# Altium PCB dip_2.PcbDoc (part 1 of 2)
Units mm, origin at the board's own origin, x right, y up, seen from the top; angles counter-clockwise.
Board outline 62.5 x 72.5 mm, 2 copper layers (Top Layer, Bottom Layer); 36 components, 64 nets, 215 pads, 49 vias.
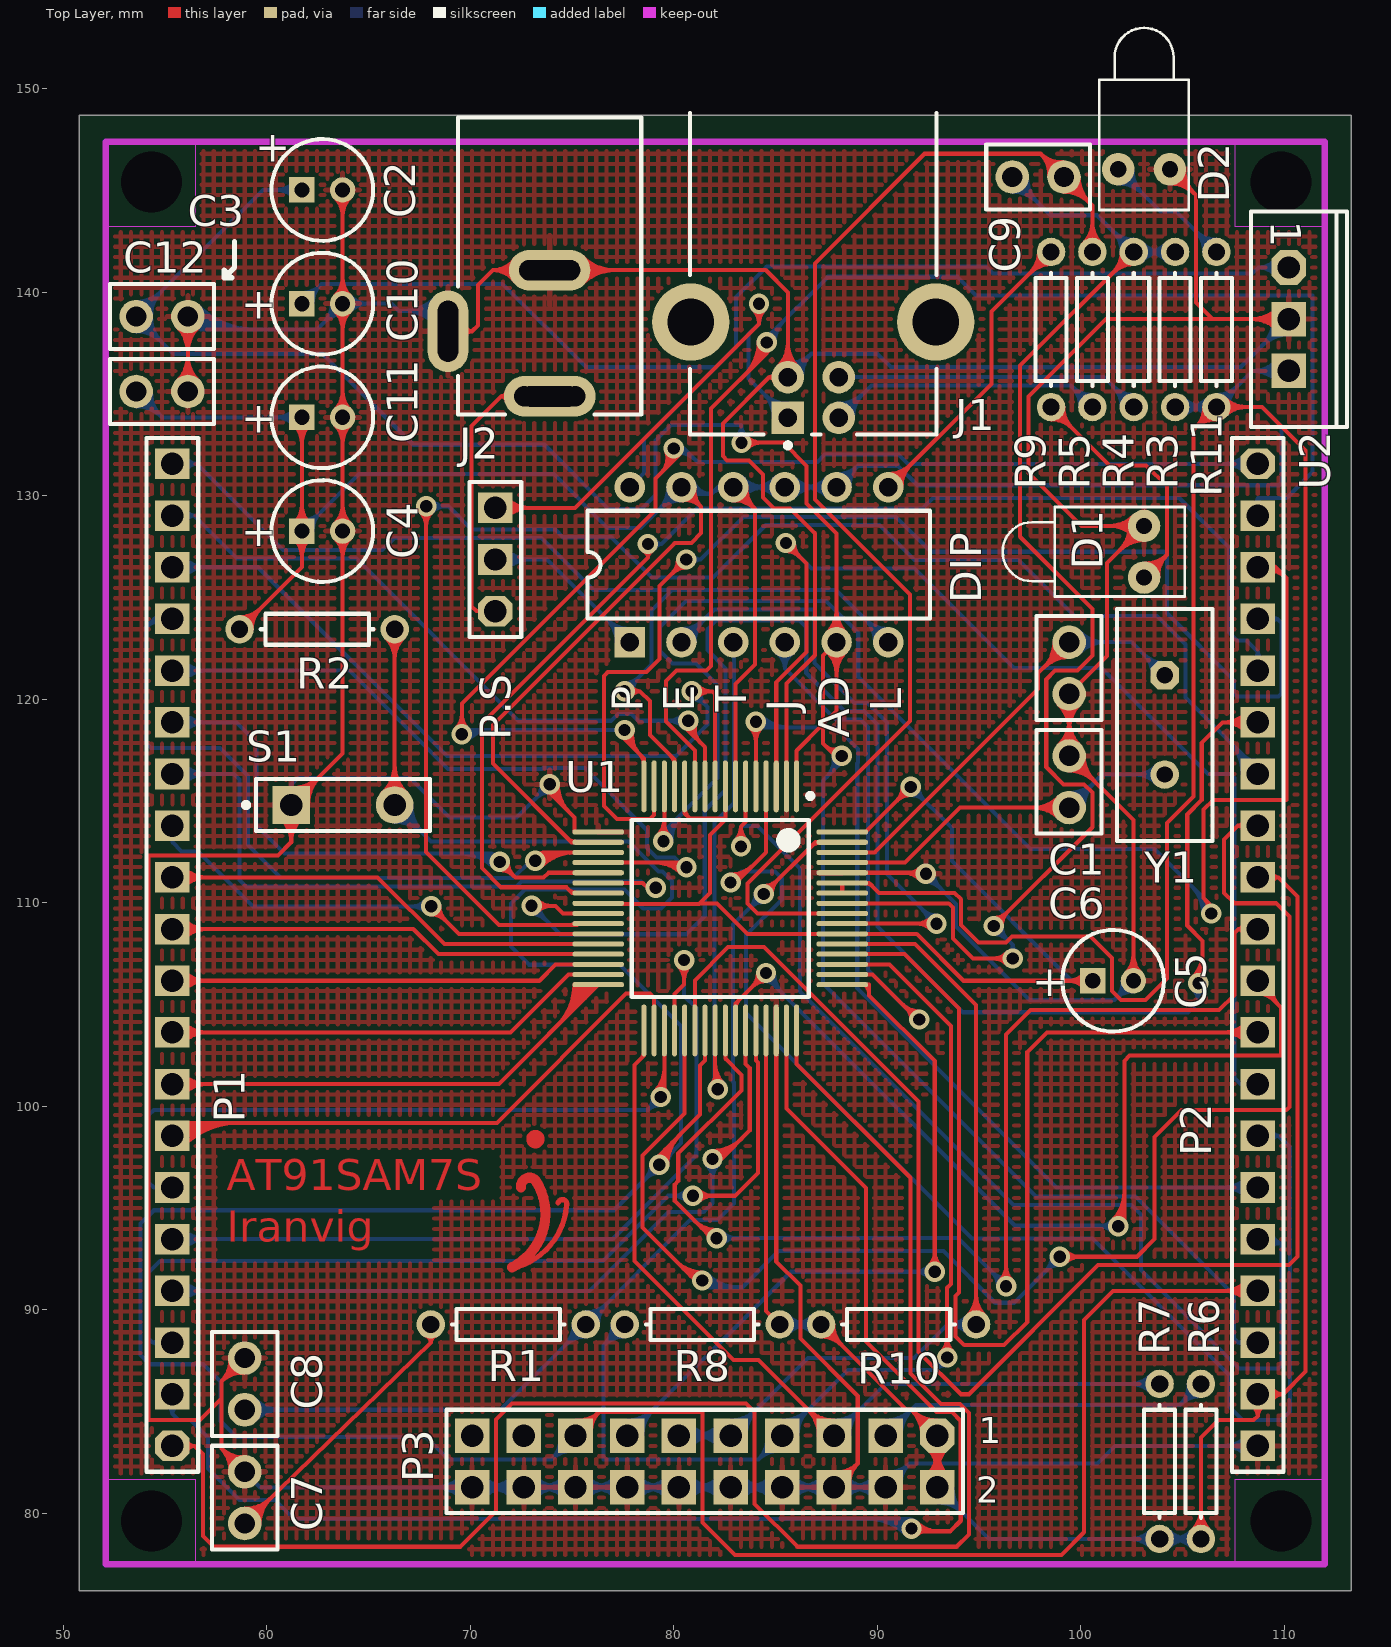
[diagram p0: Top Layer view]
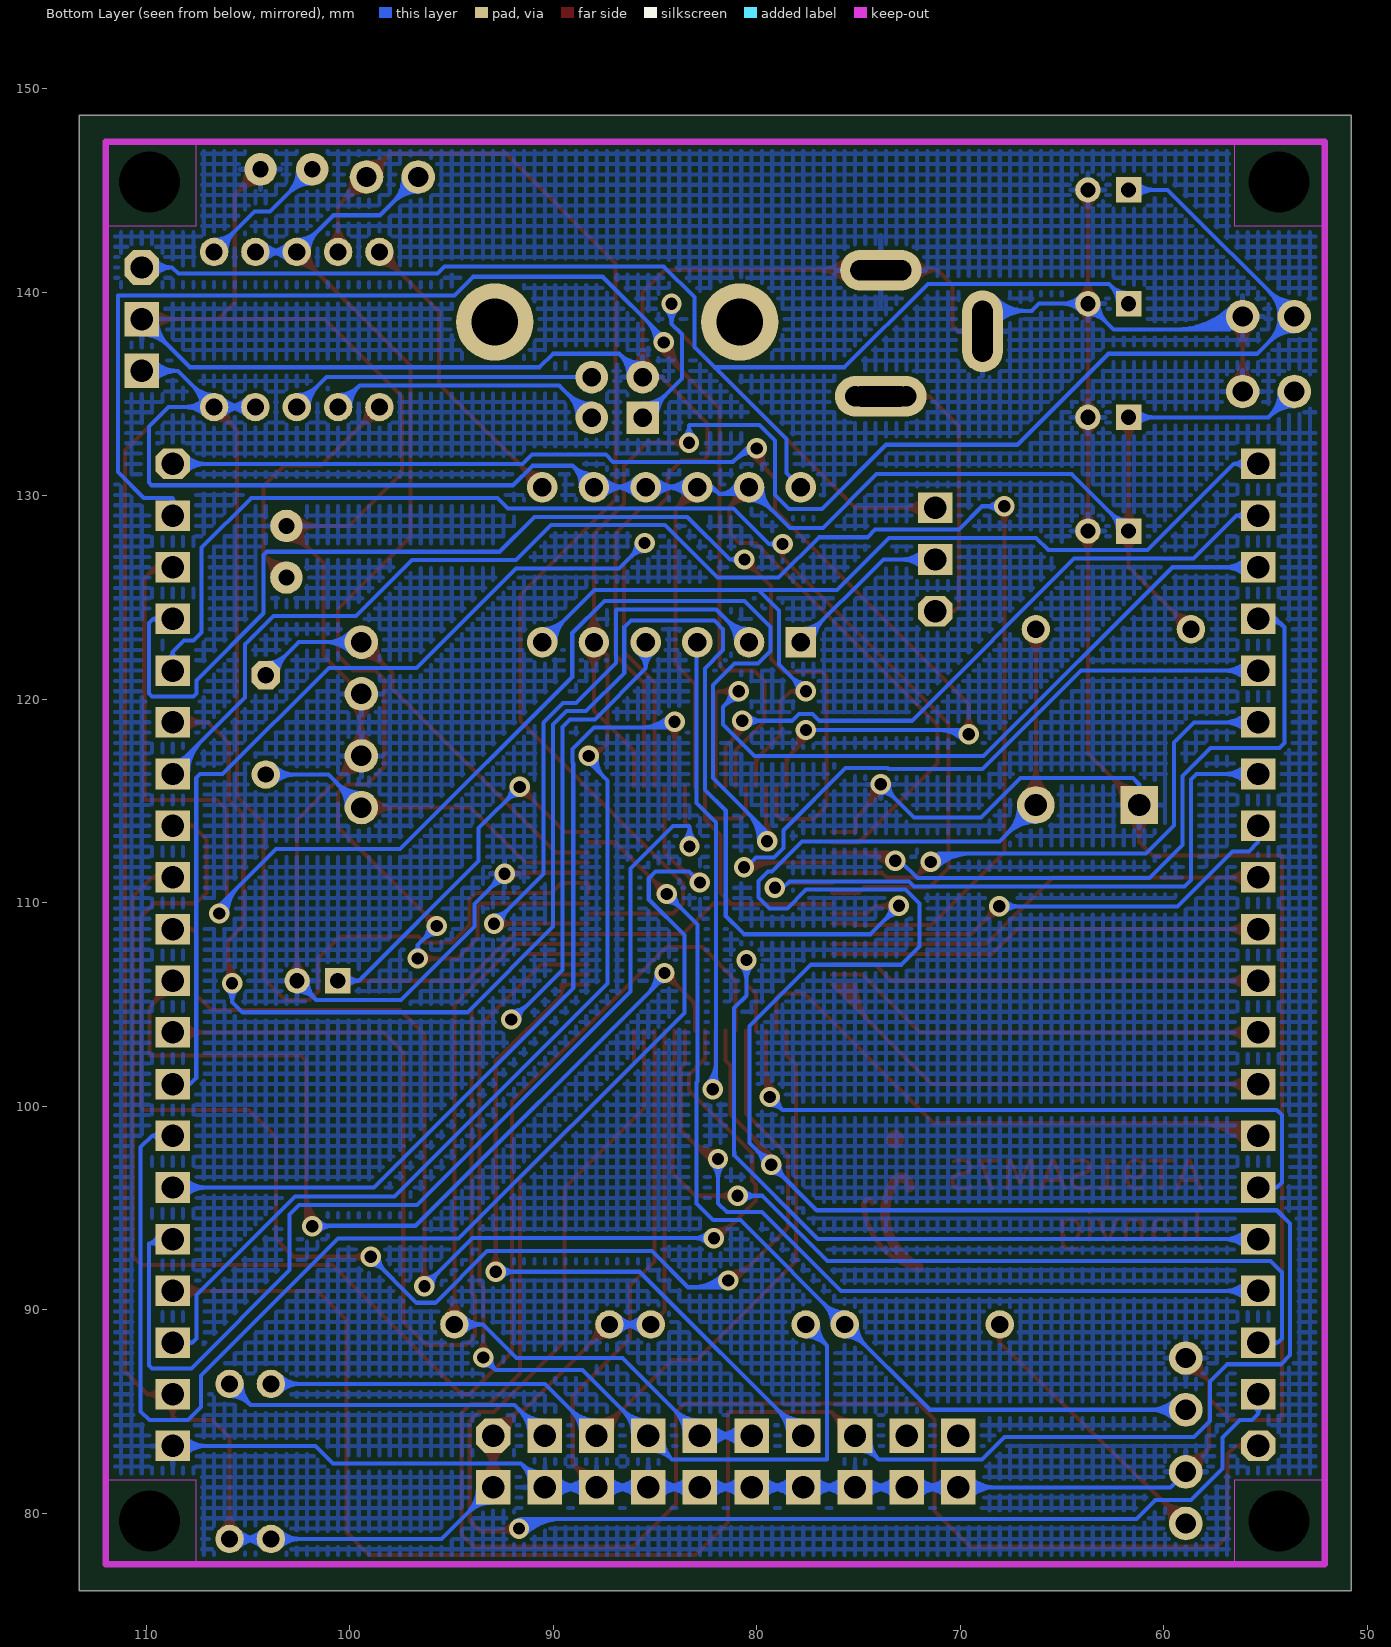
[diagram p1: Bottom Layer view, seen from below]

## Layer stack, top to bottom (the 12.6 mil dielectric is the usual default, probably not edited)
Top Layer: signal copper 0.0356
Dielectric: dielectric 0.32, FR-4, Dk 4.8
Bottom Layer: signal copper 0.0356

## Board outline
50.8,76.2 113.3,76.2 113.3,148.7 50.8,148.7

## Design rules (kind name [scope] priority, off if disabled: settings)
Clearance [All] p1: gap=0.2
PolygonConnect [All] p1: connectstyle=Relief reliefconductorwidth=0.254 reliefentries=4 polygonreliefangle="90 Angle"
RoutingVias [All] p1: holewidth=0.6 width=1 viastyle="Through Hole" minholewidth=0.711 minwidth=1.27 maxholewidth=0.711 maxwidth=1.27
SMDNeckDown [All] p1: percent=100.000
SMDToCorner [All] p1: distance=1181102
SilkscreenOverComponentPads [All] p1: minsilkscreentomaskgap=0.254
SolderMaskExpansion [All] p1: expansion=0.102
TestPointUsage [All] p1: valid=0 allowmultiple=FALSE
Testpoint [All] p1: side=15 testpointundercomponent=TRUE minsize=1.016 maxsize=2.54 preferedsize=1.524 minholesize=0 maxholesize=1.016 preferedholesize=0.813 testpointgrid=0.025 style=1023 order=0123456789
Width [All] p1: maxlimit=0.2 minlimit=0.2 preferedwidth=0.2
23 further rules are at their usual default settings.

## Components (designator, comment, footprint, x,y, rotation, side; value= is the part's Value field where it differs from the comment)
C1 "Cap" VP32-3.2 99.441,121.539 r270 top
C2 "Cap Pol1" B 62.738,145.034 r0 top
C3 "Cap" VP32-3.2 54.864,138.811 r180 top
C4 "Cap Pol1" B 62.738,128.27 r0 top
C5 "Cap Pol1" B 101.6,106.172 r0 top
C6 "Cap" VP32-3.2 99.441,115.951 r90 top
C7 "Cap" VP32-3.2 58.928,80.772 r90 top
C8 "Cap" VP32-3.2 58.928,86.36 r90 top
C9 "Cap" VP32-3.2 97.917,145.669 r180 top
C10 "Cap Pol1" B 62.738,139.446 r0 top
C11 "Cap Pol1" B 62.738,133.858 r0 top
C12 "Cap" VP32-3.2 54.864,135.128 r180 top
D1 "LED1" LED-1 103.124,127.254 r180 top
D2 "LED1" LED-1 103.124,146.05 r90 top
DIP "SW DIP-6" DIP-12/SW 84.201,126.619 r0 top (schematic designator DIPs)
J1 "1470156-1" 1470156 86.868,148.844 r90 top
J2 "PWR2.5" KLD-0202 73.914,148.59 r270 top
P1 "Header 20" HDR1X20 55.372,83.312 r90 top
P2 "Header 20" HDR1X20 108.712,131.572 r270 top
P3 "Header 10X2" HDR2X10 92.964,83.82 r180 top
P.S "Header 3" HDR1X3 71.247,124.333 r90 top (schematic designator PWR.S)
R1 "Res1" AXIAL-0.3 71.882,89.281 r180 top
R2 "Res1" AXIAL-0.3 62.484,123.444 r180 top
R3 "Res1" AXIAL-0.3 104.648,138.176 r90 top
R4 "Res1" AXIAL-0.3 102.616,138.176 r90 top
R5 "Res1" AXIAL-0.3 100.584,138.176 r90 top
R6 "Res1" AXIAL-0.3 105.918,82.55 r90 top
R7 "Res1" AXIAL-0.3 103.886,82.55 r90 top
R8 "Res1" AXIAL-0.3 81.407,89.281 r180 top
R9 "Res1" AXIAL-0.3 98.552,138.176 r90 top
R10 "Res1" AXIAL-0.3 91.059,89.281 r0 top
R11 "Res1" AXIAL-0.3 106.68,138.176 r90 top (schematic designator R13)
S1 "SW-PB" SPST-2 63.754,114.808 r0 top
U1 "AT91SAM7S256-AU-001" LQFP64_L 82.296,109.728 r270 top
U2 "LF33ACV" TO-220A 110.236,138.684 r270 top
Y1 "18.432 MHz" HC-49U 104.14,118.745 r270 top

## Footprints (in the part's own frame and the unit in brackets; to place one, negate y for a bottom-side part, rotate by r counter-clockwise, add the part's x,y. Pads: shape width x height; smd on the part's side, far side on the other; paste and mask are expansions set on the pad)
1470156 [mm] "Connector; USB1.1, Type B, Thru-Hole; 4 Position; Right Angle"
  rect 1.6x1.6 hole 0.92: 1(-15.01,1.25)
  round 1.6 hole 0.92: 2(-15.01,-1.25) 3(-13.01,-1.25) 4(-13.01,1.25)
  round 3.8 hole 2.3: 5(-10.3,6.02) 6(-10.3,-6.02)
  silkscreen extent -16.48,-6.05 -0.02,6.05
AXIAL-0.3 [mm] "Resistor; 2 Leads"
  round 1.4 hole 0.85: 1(-3.81,0) 2(3.81,0)
  silkscreen extent -2.77,-0.76 2.77,0.76
B [mm] "Capacitor, Electrolytic, Radial; Body 5 x 6.8 mm (Dia.xH typ); Pin Spacing 2 mm (typ)"
  rect 1.25x1.25 hole 0.75: 1(-1,0)
  round 1.25 hole 0.75: 2(1,0)
  silkscreen extent -2.5,-2.5 2.5,2.5
DIP-12/SW [mm] "DIP Switch; 12 Leads"
  rect 1.5x1.5 hole 0.9: 1(-6.35,-3.81)
  round 1.5 hole 0.9: 2(-3.81,-3.81) 3(-1.27,-3.81) 4(1.27,-3.81) 5(3.81,-3.81) 6(6.35,-3.81) 7(6.35,3.81) 8(3.81,3.81) 9(1.27,3.81) 10(-1.27,3.81) 11(-3.81,3.81) 12(-6.35,3.81)
  silkscreen extent -8.43,-2.65 8.41,2.65
HC-49U [mm] "Quartz Crystal, Thru-Hole; 2 Leads; Body 11.35 x 4.65 x 13.46 mm (LxWxH max)"
  oct 1.4x1.4 hole 0.8: 1(-2.44,0)
  round 1.4 hole 0.8: 2(2.44,0)
  silkscreen extent -5.7,-2.35 5.7,2.35
HDR1X3 [mm] "Connector; Header; 3 Position"
  oct 1.5x1.7 hole 1.1: 1(0,0)
  rect 1.5x1.7 hole 1.1: 2(2.54,0) 3(5.08,0)
  silkscreen extent -1.27,-1.27 6.35,1.27
HDR1X20 [mm] "Connector; Header; 20 Position"
  oct 1.5x1.7 hole 1.1: 1(0,0)
  rect 1.5x1.7 hole 1.1: 2(2.54,0) 3(5.08,0) 4(7.62,0) 5(10.16,0) 6(12.7,0) 7(15.24,0) 8(17.78,0) 9(20.32,0) 10(22.86,0) 11(25.4,0) 12(27.94,0) 13(30.48,0) 14(33.02,0) 15(35.56,0) 16(38.1,0) 17(40.64,0) 18(43.18,0) 19(45.72,0) 20(48.26,0)
  silkscreen extent -1.27,-1.27 49.53,1.27
HDR2X10 [mm] "Connector; Header; 10x2 Position"
  oct 1.7x1.7 hole 1.1: 1(0,0)
  rect 1.7x1.7 hole 1.1: 2(0,2.54) 3(2.54,0) 4(2.54,2.54) 5(5.08,0) 6(5.08,2.54) 7(7.62,0) 8(7.62,2.54) 9(10.16,0) 10(10.16,2.54) 11(12.7,0) 12(12.7,2.54) 13(15.24,0) 14(15.24,2.54) 15(17.78,0) 16(17.78,2.54) 17(20.32,0) 18(20.32,2.54) 19(22.86,0) 20(22.86,2.54)
  silkscreen extent -1.27,-1.27 24.13,3.81
KLD-0202 [mm] "DC Power Jack, 2.5mm, KLD Series, PCB Mount"
  oval 2x4.5 hole 1 slot 3 at 90 deg: 1(13.7,0)
  round 1.5 hole 1: 1A(13.7,-1.25) 1B(13.7,1.25) 2A(7.5,-1) 2B(7.5,1) 3A(9.5,-5) 3B(11.5,-5)
  oval 2x4 hole 1 slot 3 at 90 deg: 2(7.5,0)
  oval 4x2 hole 1 slot 3 at 0 deg: 3(10.5,-5)
  silkscreen extent 0,-4.5 14.6,4.5
LED-1 [mm] "Typical RED GaAs LED; 2 Leads"
  round 1.6 hole 0.8: 1(0,1.27) 2(0,-1.27)
  silkscreen extent -2,-2.2 6.95,2.2
LQFP64_L [mm] "Thin QFP, 64-Leads, Body 10x10mm, Pitch 0.5mm, IPC High Density"
  oval 2.55x0.25 smd: 1(-5.996,3.75) 2(-5.996,3.25) 3(-5.996,2.75) 4(-5.996,2.25) 5(-5.996,1.75) 6(-5.996,1.25) 7(-5.996,0.75) 8(-5.996,0.25) 9(-5.996,-0.25) 10(-5.996,-0.75) 11(-5.996,-1.25) 12(-5.996,-1.75) 13(-5.996,-2.25) 14(-5.996,-2.75) 15(-5.996,-3.25) 16(-5.996,-3.75) 33(5.996,-3.75) 34(5.996,-3.25) 35(5.996,-2.75) 36(5.996,-2.25) 37(5.996,-1.75) 38(5.996,-1.25) 39(5.996,-0.75) 40(5.996,-0.25) 41(5.996,0.25) 42(5.996,0.75) 43(5.996,1.25) 44(5.996,1.75) 45(5.996,2.25) 46(5.996,2.75) 47(5.996,3.25) 48(5.996,3.75)
  oval 0.25x2.55 smd: 17(-3.75,-5.996) 18(-3.25,-5.996) 19(-2.75,-5.996) 20(-2.25,-5.996) 21(-1.75,-5.996) 22(-1.25,-5.996) 23(-0.75,-5.996) 24(-0.25,-5.996) 25(0.25,-5.996) 26(0.75,-5.996) 27(1.25,-5.996) 28(1.75,-5.996) 29(2.25,-5.996) 30(2.75,-5.996) 31(3.25,-5.996) 32(3.75,-5.996) 49(3.75,5.996) 50(3.25,5.996) 51(2.75,5.996) 52(2.25,5.996) 53(1.75,5.996) 54(1.25,5.996) 55(0.75,5.996) 56(0.25,5.996) 57(-0.25,5.996) 58(-0.75,5.996) 59(-1.25,5.996) 60(-1.75,5.996) 61(-2.25,5.996) 62(-2.75,5.996) 63(-3.25,5.996) 64(-3.75,5.996)
  silkscreen extent -5.65,-4.35 4.35,4.55, body extent -5,-5 5,5, height 1.6
SPST-2 [mm] "Circuit Breaker; 2 Leads"
  rect 1.85x1.85 hole 1.1: 1(-2.54,0)
  round 1.85 hole 1.1: 2(2.54,0)
  silkscreen extent -4.89,-1.27 4.28,1.27
TO-220A [mm] "TO, Thru-Hole, Vertical, Heatsink Mounted; 3 In-Line Leads; Pitch 2.54 mm"
  oct 1.7x1.7 hole 1.1: 1(-2.54,0)
  rect 1.7x1.7 hole 1.1: 2(0,0) 3(2.54,0)
  silkscreen extent -5.3,-1.85 5.3,2.85
VP32-3.2 [mm] "Capacitor, Ceramic, Thru-Hole, Dipped Radial; Body 5.1 x 3.2 mm (WxT) Pin Spacing 2.54 mm (typ)"
  round 1.65 hole 1: 1(-1.27,0) 2(1.27,0)
  silkscreen extent -2.55,-1.6 2.55,1.6

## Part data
C1 C3 C6 C7 C8 C9 C12: "Capacitor"
C2 C4 C5 C10 C11: "Polarized Capacitor (Radial)"
D1 D2: "Typical RED GaAs LED"
DIP: "DIP Switch, 6 Position, SPST"
J1: "USB 1.1, Right Angle, Thru-Hole, B Type, Receptacle, 4 Position, White"
J2: "Low Voltage Power Supply Connector"
P1 P2: "Header, 20-Pin"
P3: "Header, 10-Pin, Dual row"
P.S: "Header, 3-Pin"
R1 R2 R3 R4 R5 R6 R7 R8 R9 R10 R11: "Resistor"
S1: "Switch"
U1: "Smart ARM Microcontroller, ARM7TDMI 32-Bit RISC CPU, 256KB Flash and 64KB SRAM, 64-Pin LQFP, Industrial, Pb-Free"
U2: "500mA, Very Low Drop (0.45V) Voltage Regulator with Dump Protection (40V)"
Y1: library part ECS-10-13-1, "Crystal Oscillator"

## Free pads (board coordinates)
  round 1.524 hole 3: 3(54.356,79.629) 3(54.356,145.415) 3(109.855,79.629) 3(109.855,145.415)

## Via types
v1: diameter 1, hole 0.6, Top Layer to Bottom Layer, 49 vias

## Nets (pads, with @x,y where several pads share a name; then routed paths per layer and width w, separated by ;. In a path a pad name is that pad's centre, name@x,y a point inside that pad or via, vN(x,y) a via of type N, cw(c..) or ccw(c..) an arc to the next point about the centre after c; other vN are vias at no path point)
3.3V: C4.1 C11.1 C12.2 DIP.8 DIP.9 DIP.10 DIP.11 P2.19 P3.1 P3.2 R2.2 R3.1 R6.1 R7.1 R8.1 R10.1 R11.1 U1.7 U1.18 U1.45 U1.58 U1.59 U2.3 | length 420.7
  Top Layer w0.2: R2.2@58.674,123.444 61.738,126.508 C4.1@61.738,128.27 C11.1@61.738,133.858 ; R2.2@58.674,123.844 ccw(c58.674,124.81) 59.357,124.127 ccw(c60.04,123.444) R2.2@59.074,123.444 ; R2.2@58.674,124.044 ccw(c58.674,125.493) 59.698,124.468 ccw(c60.723,123.444) R2.2@59.274,123.444 ; C4.1@61.367,127.899 cw(c60.471,127.003) 61.738,127.003 cw(c63.005,127.003) C4.1@62.109,127.899 ; C4.1@61.367,128.641 ccw(c60.471,129.537) 61.738,129.537 ccw(c63.005,129.537) C4.1@62.109,128.641 ; C11.1@61.367,133.487 cw(c60.471,132.591) 61.738,132.591 cw(c63.005,132.591) C11.1@62.109,133.487 ; C4.1@61.508,128.04 cw(c60.953,127.485) 61.738,127.485 cw(c62.523,127.485) C4.1@61.968,128.04 ; C4.1@61.508,128.5 ccw(c60.953,129.055) 61.738,129.055 ccw(c62.523,129.055) C4.1@61.968,128.5 ; C11.1@61.508,133.628 cw(c60.953,133.073) 61.738,133.073 cw(c62.523,133.073) C11.1@61.968,133.628 ; 74.821,113.139 ccw(c75.15,113.469) U1.18@75.15,113.003 ; U1.18@76.3,112.978 74.982,112.978 71.12,116.84 71.12,118.745 80.061,127.686 80.874,127.686 81.356,128.168 81.356,129.464 ; DIP.11@80.391,130.429 81.356,129.464 ; DIP.11@80.437,129.981 cw(c80.517,129.218) 81.059,129.761 cw(c81.602,130.303) DIP.11@80.839,130.383 ; DIP.11@80.458,129.782 cw(c80.573,128.68) 81.356,129.464 ; DIP.11@81.038,130.362 ccw(c82.14,130.247) 81.356,129.464 ; DIP.10@82.931,130.429 83.998,129.362 ; DIP.10@82.944,129.979 cw(c82.972,128.993) 83.67,129.69 cw(c84.367,130.388) DIP.10@83.381,130.416 ; DIP.10@82.949,129.779 cw(c82.99,128.354) 83.998,129.362 ; U1.7@83.046,115.724 83.046,120.765 83.998,121.717 83.998,129.362 ; DIP.10@83.581,130.411 ccw(c85.006,130.37) 83.998,129.362 ; U1.45@84.546,103.732 84.546,89.952 R8.1@85.217,89.281 ; R10.1@87.249,88.681 cw(c87.249,87.232) 88.273,88.257 cw(c89.298,89.281) R10.1@87.849,89.281 ; R10.1@87.249,88.881 cw(c87.249,87.915) 87.932,88.598 cw(c88.615,89.281) R10.1@87.649,89.281 ; R10.1@87.249,89.281 91.441,85.089 91.695,85.089 ; U1.58@88.292,110.478 U1.59@88.292,110.978 89.611,110.978 90.099,110.49 93.814,110.49 94.126,110.178 94.126,108.922 94.991,108.057 96.334,108.057 96.633,108.356 100.482,108.356 101.549,107.29 101.549,105.664 101.981,105.232 103.2,105.232 104.259,106.291 104.259,113.924 105.556,115.222 105.556,133.242 R11.1@106.68,134.366 108.915,134.366 111.062,132.219 111.062,86.97 109.944,85.852 ; U1.59@89.442,110.953 cw(c89.442,110.484) 89.773,110.816 ; U1.59@89.449,110.954 cw(c89.522,110.72) 89.696,110.893 ; P3.1@92.214,83.825 ccw(c90.443,83.836) 91.695,85.089 ; P3.1@92.414,83.824 ccw(c91.115,83.832) 92.034,84.75 ccw(c92.952,85.669) P3.1@92.96,84.37 ; P3.2@92.434,81.81 ccw(c91.153,83.091) 92.964,83.091 ccw(c94.775,83.091) P3.2@93.494,81.81 ; P3.1@92.434,83.29 cw(c91.153,82.009) 92.964,82.009 cw(c94.775,82.009) P3.1@93.494,83.29 ; P3.2@92.575,81.669 ccw(c91.636,82.608) 92.964,82.608 ccw(c94.292,82.608) P3.2@93.353,81.669 ; P3.1@92.575,83.431 cw(c91.636,82.492) 92.964,82.492 cw(c94.292,82.492) P3.1@93.353,83.431 ; P3.1@92.959,84.57 cw(c92.948,86.341) 91.695,85.089 ; P3.2@92.964,81.28 P3.1@92.964,83.82 91.695,85.089 ; R6.1@105.494,79.164 ccw(c104.469,80.189) 105.918,80.189 ccw(c107.367,80.189) R6.1@106.342,79.164 ; R6.1@105.635,79.023 ccw(c104.952,79.706) 105.918,79.706 ccw(c106.884,79.706) R6.1@106.201,79.023 ; R6.1@105.918,78.74 105.918,83.718 106.782,84.582 108.509,84.582 108.712,84.785 ; R11.1@106.08,134.366 cw(c104.631,134.366) 105.656,133.342 cw(c106.68,132.317) R11.1@106.68,133.766 ; R11.1@106.28,134.366 cw(c105.314,134.366) 105.997,133.683 cw(c106.68,133) R11.1@106.68,133.966 ; R11.1@106.963,134.083 cw(c107.646,133.4) 107.646,134.366 cw(c107.646,135.332) R11.1@106.963,134.649 ; R11.1@107.104,133.942 cw(c108.129,132.917) 108.129,134.366 cw(c108.129,135.815) R11.1@107.104,134.79 ; P2.19@108.414,85.274 cw(c108.162,84.785) 108.712,84.785 ; P2.19@109.01,85.274 ccw(c109.262,84.785) 108.712,84.785 ; P2.19@109.201,85.625 cw(c109.596,85.394) 109.596,85.852 cw(c109.596,86.31) P2.19@109.201,86.079 ; P2.19@109.373,85.524 cw(c109.944,85.191) 109.944,85.852 ; P2.19@109.373,86.18 ccw(c109.944,86.513) 109.944,85.852 ; 108.712,84.785 P2.19@108.712,85.852 109.944,85.852
  Bottom Layer w0.2: C12.2@53.594,134.403 cw(c53.594,132.653) 54.832,133.89 cw(c56.069,135.128) C12.2@54.319,135.128 ; C12.2@53.594,134.603 cw(c53.594,133.336) 54.49,134.232 cw(c55.386,135.128) C12.2@54.119,135.128 ; C12.2@53.594,135.128 54.864,133.858 C11.1@61.738,133.858 ; C11.1@61.367,133.487 ccw(c60.471,132.591) 60.471,133.858 ccw(c60.471,135.125) C11.1@61.367,134.229 ; C11.1@61.508,133.628 ccw(c60.953,133.073) 60.953,133.858 ccw(c60.953,134.643) C11.1@61.508,134.088 ; C4.1@61.738,128.27 64.532,131.064 74.117,131.064 76.759,128.422 78.384,128.422 DIP.11@80.391,130.429 80.729,130.091 81.841,130.091 ; C4.1@61.738,128.595 ccw(c61.738,129.38) 62.293,128.825 ccw(c62.848,128.27) C4.1@62.063,128.27 ; C4.1@61.738,128.795 ccw(c61.738,130.062) 62.634,129.166 ccw(c63.53,128.27) C4.1@62.263,128.27 ; DIP.11@79.741,130.429 cw(c78.172,130.429) 79.281,129.319 cw(c80.391,128.21) DIP.11@80.391,129.779 ; DIP.11@79.941,130.429 cw(c78.855,130.429) 79.623,129.661 cw(c80.391,128.893) DIP.11@80.391,129.979 ; DIP.11@80.624,130.52 ccw(c81.254,130.768) 81.254,130.091 ; DIP.11@80.81,130.593 ccw(c81.548,130.883) 81.548,130.091 ; DIP.11@80.851,129.969 cw(c81.143,129.677) 81.143,130.091 ; DIP.11@80.996,130.667 ccw(c81.841,130.998) 81.841,130.091 ; 81.834,130.084 cw(c82.404,129.514) DIP.10@82.806,130.212 ; 82.019,130.268 cw(c82.539,129.748) DIP.10@82.906,130.386 ; DIP.10@83.249,130.111 cw(c84.017,129.343) 84.017,130.429 cw(c84.017,131.515) DIP.10@83.249,130.747 ; DIP.10@83.391,129.969 cw(c84.5,128.86) 84.5,130.429 cw(c84.5,131.998) DIP.10@83.391,130.889 ; DIP.9@85.011,129.969 ccw(c83.902,128.86) 83.902,130.429 ccw(c83.902,131.998) DIP.9@85.011,130.889 ; DIP.9@85.153,130.111 ccw(c84.385,129.343) 84.385,130.429 ccw(c84.385,131.515) DIP.9@85.153,130.747 ; R8.1@85.217,89.281 R10.1@87.249,89.281 ; R8.1@85.5,88.998 cw(c86.183,88.315) 86.183,89.281 cw(c86.183,90.247) R8.1@85.5,89.564 ; R8.1@85.641,88.857 cw(c86.666,87.832) 86.666,89.281 cw(c86.666,90.73) R8.1@85.641,89.705 ; DIP.9@85.789,130.111 cw(c86.557,129.343) 86.557,130.429 cw(c86.557,131.515) DIP.9@85.789,130.747 ; DIP.9@85.931,129.969 cw(c87.04,128.86) 87.04,130.429 cw(c87.04,131.998) DIP.9@85.931,130.889 ; R10.1@86.825,88.857 ccw(c85.8,87.832) 85.8,89.281 ccw(c85.8,90.73) R10.1@86.825,89.705 ; R10.1@86.966,88.998 ccw(c86.283,88.315) 86.283,89.281 ccw(c86.283,90.247) R10.1@86.966,89.564 ; DIP.8@87.551,129.969 ccw(c86.442,128.86) 86.442,130.429 ccw(c86.442,131.998) DIP.8@87.551,130.889 ; DIP.8@87.693,130.111 ccw(c86.925,129.343) 86.925,130.429 ccw(c86.925,131.515) DIP.8@87.693,130.747 ; DIP.8@88.029,130.879 ccw(c88.067,131.827) 88.738,131.156 ccw(c89.409,130.485) DIP.8@88.461,130.447 ; DIP.8@88.037,131.078 ccw(c88.091,132.448) 89.061,131.479 ; DIP.8@88.66,130.455 cw(c90.03,130.509) 89.061,131.479 ; P3.2@92.964,80.53 cw(c92.964,78.719) 94.244,80 cw(c95.525,81.28) P3.2@93.714,81.28 ; P3.2@92.964,80.73 cw(c92.964,79.402) 93.903,80.341 cw(c94.842,81.28) P3.2@93.514,81.28 ; P3.2@92.964,81.28 95.504,78.74 R7.1@103.886,78.74 R6.1@105.918,78.74 ; R7.1@103.462,78.316 ccw(c102.437,77.291) 102.437,78.74 ccw(c102.437,80.189) R7.1@103.462,79.164 ; R7.1@103.603,78.457 ccw(c102.92,77.774) 102.92,78.74 ccw(c102.92,79.706) R7.1@103.603,79.023 ; R7.1@104.169,78.457 cw(c104.852,77.774) 104.852,78.74 cw(c104.852,79.706) R7.1@104.169,79.023 ; R7.1@104.31,78.316 cw(c105.335,77.291) 105.335,78.74 cw(c105.335,80.189) R7.1@104.31,79.164 ; R3.1@104.648,134.366 R11.1@106.68,134.366 ; R3.1@104.931,134.083 cw(c105.614,133.4) 105.614,134.366 cw(c105.614,135.332) R3.1@104.931,134.649 ; R3.1@105.072,133.942 cw(c106.097,132.917) 106.097,134.366 cw(c106.097,135.815) R3.1@105.072,134.79 ; R6.1@105.494,78.316 ccw(c104.469,77.291) 104.469,78.74 ccw(c104.469,80.189) R6.1@105.494,79.164 ; R6.1@105.635,78.457 ccw(c104.952,77.774) 104.952,78.74 ccw(c104.952,79.706) R6.1@105.635,79.023 ; R11.1@106.256,133.942 ccw(c105.231,132.917) 105.231,134.366 ccw(c105.231,135.815) R11.1@106.256,134.79 ; R11.1@106.397,134.083 ccw(c105.714,133.4) 105.714,134.366 ccw(c105.714,135.332) R11.1@106.397,134.649 ; R11.1@106.68,134.766 ccw(c106.68,135.732) 107.363,135.049 ccw(c108.046,134.366) R11.1@107.08,134.366 ; R11.1@106.68,134.966 ccw(c106.68,136.415) 107.704,135.39 ccw(c108.729,134.366) R11.1@107.28,134.366 ; R11.1@106.963,134.083 cw(c107.646,133.4) 107.646,134.366 cw(c107.646,135.332) R11.1@106.963,134.649 ; R11.1@107.104,133.942 cw(c108.129,132.917) 108.129,134.366 cw(c108.129,135.815) R11.1@107.104,134.79 ; U2.3@109.699,135.621 ccw(c108.458,134.412) 108.458,136.144 ; U2.3@109.699,136.667 cw(c108.458,137.876) 108.458,136.144 ; U2.3@109.842,135.76 ccw(c108.932,134.874) 108.932,136.144 ccw(c108.932,137.414) U2.3@109.842,136.528 ; U2.3@110.236,136.144 108.458,136.144 ; 81.841,130.091 82.179,130.429 DIP.10@82.931,130.429 DIP.9@85.471,130.429 DIP.8@88.011,130.429 89.061,131.479 ; 89.061,131.479 91.034,131.479 91.991,130.522 109.753,130.522 109.88,130.649 109.88,133.401 108.915,134.366 R11.1@106.68,134.366 ; R11.1@106.68,134.366 108.458,136.144
"+5V USB": C10.1 DIP.12 U2.1 | length 72.7
  Bottom Layer w0.2: C10.1@61.738,139.446 62.703,140.411 71.603,140.411 75.692,136.322 82.093,136.322 83.075,137.304 ; C10.1@61.738,139.771 ccw(c61.738,140.556) 62.293,140.001 ccw(c62.848,139.446) C10.1@62.063,139.446 ; C10.1@61.738,139.971 ccw(c61.738,141.238) 62.634,140.342 ccw(c63.53,139.446) C10.1@62.263,139.446 ; DIP.12@77.851,130.429 78.554,131.132 78.554,132.783 83.075,137.304 ; U2.1@109.636,140.774 ccw(c108.737,140.102) 108.737,141.224 ; U2.1@109.636,141.674 cw(c108.737,142.346) 108.737,141.224 ; U2.1@109.796,140.894 ccw(c109.137,140.401) 109.137,141.224 ccw(c109.137,142.047) U2.1@109.796,141.554 ; U2.1@110.236,141.224 108.737,141.224 ; 83.075,137.304 83.075,139.768 ; 83.075,137.304 83.075,139.768 ; 83.075,139.768 84.582,141.275 95.352,141.275 95.707,140.919 108.433,140.919 108.737,141.224
A20: P2.1 U1.16 | length 76.8
  Top Layer w0.2: v1@69.313,118.571 ccw(c68.63,119.253) 69.596,119.253 ccw(c70.562,119.253) v1@69.879,118.571 ; v1(69.596,118.288) 69.596,119.786 79.121,129.311 79.121,130.861 80.289,132.029 80.289,132.055 v1(80.01,132.334) cw(c79.355,132.085) 79.85,131.59 ; 77.792,117.848 cw(c78.297,118.352) v1(77.597,118.491) 77.597,118.043 78.546,117.094 U1.16@78.546,115.724 ; v1@77.793,118.452 ccw(c78.739,118.265) 78.057,117.583 ; v1@77.989,118.413 ccw(c79.181,118.177) 78.322,117.318 ; 78.348,117.292 cw(c77.93,116.874) U1.16@78.521,116.874 ; 79.413,131.153 ccw(c78.721,131.845) v1@79.636,132.192 ; 79.632,131.372 ccw(c79.038,131.965) v1@79.823,132.263 ; 80.069,131.809 ccw(c79.672,132.206) v1@80.197,132.405
  Bottom Layer w0.2: v1@69.737,118.146 cw(c70.569,117.314) 70.569,118.491 ; v1@69.879,118.005 cw(c71.052,116.832) 71.052,118.491 ; v1@69.879,118.571 ccw(c70.071,118.763) 70.071,118.491 ; 70.087,118.491 ccw(c70.087,117.797) v1(69.596,118.288) 69.799,118.491 v1(77.597,118.491) ; v1@80.025,132.135 cw(c80.132,130.735) 81.125,131.727 ; 80.817,132.035 ccw(c80.088,131.307) v1(80.01,132.334) 80.518,132.334 81.178,131.674 87.071,131.674 87.427,132.029 91.059,132.029 91.516,131.572 P2.1@108.712,131.572 ; P2.1@108.152,131.112 ccw(c107.043,130.003) 107.043,131.572 ccw(c107.043,133.141) P2.1@108.152,132.032 ; P2.1@108.294,131.254 ccw(c107.526,130.486) 107.526,131.572 ccw(c107.526,132.658) P2.1@108.294,131.89
A21: P2.2 U1.11 | length 74.4
  Top Layer w0.2: U1.11@81.046,115.724 81.046,117.492 79.629,118.909 79.629,120.904 80.137,121.412 81.624,121.412 81.841,121.629 81.841,134.292 84.582,137.033 v1(84.582,137.541) cw(c83.356,137.541) 84.223,136.674 ; 83.54,135.991 ccw(c81.99,137.541) v1@84.182,137.541 ; 83.881,136.332 ccw(c82.673,137.541) v1@84.382,137.541 ; 84.564,137.015 ccw(c84.038,137.541) v1@84.782,137.541
  Bottom Layer w0.2: v1(84.582,137.541) 84.665,137.541 84.675,137.551 84.675,137.863 87.579,140.767 93.955,140.767 94.869,139.852 111.404,139.852 111.404,131.166 110.134,129.896 108.712,129.896 ; v1@84.582,137.941 ccw(c84.582,138.355) 84.875,138.062 ; v1@84.782,137.541 cw(c85.817,137.541) 85.085,138.273 ; v1@84.982,137.541 cw(c86.5,137.541) 85.426,138.614 ; P2.2@108.532,129.657 ccw(c108.463,129.896) 108.712,129.896 ; P2.2@108.712,129.032 108.712,129.896 ; P2.2@108.892,129.657 cw(c108.961,129.896) 108.712,129.896
A22: P2.3 U1.14 | length 87.3
  Top Layer w0.2: v1@79.219,113.313 ccw(c78.43,114.102) 79.546,114.102 ; v1@79.361,113.171 ccw(c78.913,113.619) 79.546,113.619 ; v1(79.502,113.03) 79.546,113.074 U1.14@79.546,115.724 ; 79.546,113.889 ccw(c80.361,113.889) v1@79.785,113.313 ; 106.082,110.199 cw(c105.628,109.744) v1@106.237,109.538 ; 106.31,109.971 cw(c105.968,109.629) v1(106.426,109.474) 106.426,109.855 106.045,110.236 106.045,114.579 106.528,115.062 110.109,115.062 110.109,125.959 109.576,126.492 P2.3@108.712,126.492 ; P2.3@108.758,126.632 cw(c109.047,125.877) 109.619,126.449 ; P2.3@108.83,126.445 cw(c109.168,125.562) 109.837,126.231 ; P2.3@108.901,126.259 cw(c109.289,125.247) 110.055,126.013
  Bottom Layer w0.2: v1@79.702,113.03 cw(c81.289,113.03) 80.167,114.152 ; 79.825,113.81 ccw(c80.606,113.03) v1(79.502,113.03) 79.502,113.487 82.156,116.141 82.156,120.714 81.111,121.759 79.956,121.759 79.341,122.374 79.341,123.562 80.62,124.841 87.503,124.841 89.078,123.266 89.078,121.107 97.536,112.649 103.632,112.649 106.426,109.855 v1(106.426,109.474) ccw(c105.506,109.474) 106.157,110.124 ; v1@79.902,113.03 cw(c81.971,113.03) 80.508,114.493 ; 105.474,110.807 cw(c104.141,109.474) v1@106.026,109.474 ; 105.815,110.466 cw(c104.823,109.474) v1@106.226,109.474
A23: P2.4 U1.15 | length 62.8
  Top Layer w0.2: U1.15@79.046,115.724 79.046,114.327 78.842,114.122 77.216,114.122 76.581,114.757 76.581,121.158 76.768,121.345 78.673,121.345 79.312,121.984 79.312,125.565 v1(80.62,126.873) ; v1@80.22,126.873 cw(c79.254,126.873) 79.937,126.19 cw(c80.62,125.507) v1@80.62,126.473
  Bottom Layer w0.2: v1(80.62,126.873) 81.331,126.873 ; v1@80.961,126.665 cw(c81.331,126.44) 81.331,126.873 ; v1@80.961,127.081 ccw(c81.331,127.306) 81.331,126.873 ; P2.4@108.712,123.952 109.677,123.952 ; P2.4@109.436,123.771 cw(c109.677,123.701) 109.677,123.952 ; P2.4@109.436,124.133 ccw(c109.677,124.203) 109.677,123.952 ; 81.331,126.873 83.426,128.968 90.932,128.968 92.646,127.254 104.089,127.254 104.242,127.102 104.242,124.231 107.544,120.929 107.544,120.294 107.696,120.142 109.728,120.142 109.88,120.294 109.88,123.749 109.677,123.952
A24: P2.5 U1.23 | length 65.5
  Top Layer w0.2: 74.882,110.614 ccw(c75.15,110.882) U1.23@75.15,110.503 ; U1.23@76.3,110.478 75.018,110.478 74.73,110.766 71.526,110.766 70.59,111.703 70.59,118.824 78.74,126.975 ; v1@78.555,127.28 cw(c78.395,126.975) 78.74,126.975 ; v1(78.74,127.635) 78.74,126.975 ; v1@78.925,127.28 ccw(c79.085,126.975) 78.74,126.975
  Bottom Layer w0.2: v1(78.74,127.635) 79.4,127.635 ; v1@79.095,127.45 cw(c79.4,127.29) 79.4,127.635 ; v1@79.095,127.82 ccw(c79.4,127.98) 79.4,127.635 ; P2.5@108.498,122.026 ccw(c108.394,122.326) 108.712,122.326 ; P2.5@108.712,121.412 108.712,122.326 ; P2.5@108.926,122.026 cw(c109.03,122.326) 108.712,122.326 ; 79.4,127.635 81.144,129.379 92.244,129.379 92.761,129.896 104.851,129.896 107.29,127.457 107.29,123.292 107.696,122.885 108.153,122.885 108.712,122.326
A25: P2.6 U1.25 | length 95.6
  Top Layer w0.2: v1(73.025,109.855) 74.193,109.855 74.57,109.478 U1.25@76.3,109.478 ; v1@73.308,109.572 cw(c73.991,108.889) 73.991,109.855 cw(c73.991,110.821) v1@73.308,110.138 ; v1@105.508,106.328 ccw(c104.335,107.501) 105.994,107.501 ; v1@105.65,106.186 ccw(c104.818,107.018) 105.994,107.018 ; 105.994,106.52 ccw(c106.266,106.52) v1@106.074,106.328 ; 105.994,106.536 cw(c105.3,106.536) v1(105.791,106.045) 105.994,106.248 105.994,108.128 105.245,108.877 105.245,114.345 105.956,115.056 105.956,117.856 106.972,118.872 P2.6@108.712,118.872 ; P2.6@108.152,118.412 ccw(c107.043,117.303) 107.043,118.872 ccw(c107.043,120.441) P2.6@108.152,119.332 ; P2.6@108.294,118.554 ccw(c107.526,117.786) 107.526,118.872 ccw(c107.526,119.958) P2.6@108.294,119.19
  Bottom Layer w0.2: v1@73.025,109.455 cw(c73.025,108.489) 73.708,109.172 cw(c74.391,109.855) v1@73.425,109.855 ; v1(73.025,109.855) 74.422,108.458 80.645,108.458 81.534,109.347 81.534,114.529 82.563,115.557 82.563,121.526 81.661,122.428 81.661,123.444 82.093,123.876 86.191,123.876 86.521,123.546 86.521,121.302 88.405,119.418 89.358,119.418 90.018,118.759 90.018,108.839 94.234,104.623 105.283,104.623 105.791,105.131 ; v1@105.52,105.751 cw(c104.946,105.131) 105.791,105.131 ; v1(105.791,106.045) 105.791,105.131 ; v1@106.062,105.751 ccw(c106.636,105.131) 105.791,105.131
A26: P2.7 U1.26 | length 85.3
  Top Layer w0.2: v1@67.561,129.206 cw(c66.878,128.524) 67.843,128.524 cw(c68.809,128.524) v1@68.126,129.206 ; v1(67.843,129.489) 67.843,112.497 71.425,108.915 75.26,108.915 75.26,108.978 U1.26@76.3,108.978 ; 74.938,108.915 ccw(c74.938,109.19) U1.26@75.132,108.996
  Bottom Layer w0.2: v1(67.843,129.489) 68.936,129.489 70.079,128.346 74.193,128.346 74.574,127.965 76.962,127.965 78.943,125.984 81.947,125.984 84.531,128.568 90.126,128.568 91.846,126.848 96.952,126.848 99.695,124.104 103.759,124.104 105.156,122.707 105.156,120.09 108.712,116.534 P2.7@108.712,116.332 ; v1@68.126,129.206 cw(c68.809,128.524) 68.809,129.489 cw(c68.809,130.455) v1@68.126,129.772 ; 107.289,117.957 cw(c105.663,116.332) P2.7@107.962,116.332 ; 107.63,117.616 cw(c106.346,116.332) P2.7@108.162,116.332 ; 107.972,117.275 cw(c107.029,116.332) P2.7@108.362,116.332 ; 108.018,117.228 ccw(c108.612,117.822) P2.7@108.612,116.982
A27: P2.8 U1.37 | length 80.3
  Top Layer w0.2: 80.16,92.356 ccw(c81.407,93.603) v1@81.407,91.84 ; 80.502,92.015 ccw(c81.407,92.92) v1@81.407,91.64 ; U1.37@80.546,103.732 80.546,99.647 78.478,97.578 78.478,94.039 81.077,91.44 v1(81.407,91.44) cw(c81.407,92.237) 80.843,91.673 ; v1(98.984,92.608) 102.768,92.608 103.632,93.472 103.632,98.501 104.953,99.822 110.109,99.822 110.262,99.975 110.262,109.328 109.608,109.982 107.569,109.982 107.061,110.49 107.061,113.106 107.747,113.792 ; v1@99.267,92.326 cw(c99.949,91.643) 99.949,92.608 cw(c99.949,93.574) v1@99.267,92.891 ; P2.8@107.988,113.611 ccw(c107.747,113.541) 107.747,113.792 ; P2.8@107.988,113.973 cw(c107.747,114.043) 107.747,113.792 ; P2.8@108.712,113.792 107.747,113.792
  Bottom Layer w0.2: v1@81.548,91.581 ccw(c82.687,92.72) 82.687,91.11 ; v1@81.69,91.723 ccw(c83.17,93.203) 83.17,91.11 ; 82.204,91.11 cw(c82.204,92.237) v1(81.407,91.44) 81.737,91.11 83.388,91.11 85.166,92.888 93.269,92.888 95.809,90.348 96.723,90.348 v1(98.984,92.608) ; v1@98.584,92.608 cw(c97.618,92.608) 98.301,91.926 cw(c98.984,91.243) v1@98.984,92.208
A28: P2.9 U1.38 | length 72.7
  Top Layer w0.2: U1.38@81.046,103.732 81.046,106.192 82.677,107.823 84.455,107.823 92.037,100.241 92.037,87.932 94.117,85.852 94.513,85.852 100.863,92.202 110.236,92.202 110.662,92.628 110.662,110.318 109.728,111.252 ; P2.9@108.712,111.252 109.728,111.252 ; P2.9@109.426,111.037 cw(c109.728,110.932) 109.728,111.252 ; P2.9@109.426,111.467 ccw(c109.728,111.572) 109.728,111.252
A29: P2.10 U1.41 | length 64.3
  Top Layer w0.2: 81.034,94.372 ccw(c82.118,95.456) v1@82.118,93.923 ; 81.375,94.03 ccw(c82.118,94.773) v1@82.118,93.723 ; 81.602,93.804 cw(c81.32,93.523) v1@81.718,93.523 ; v1(82.118,93.523) 81.883,93.523 80.061,95.345 80.061,96.158 80.23,96.327 80.23,97.68 83.337,100.787 83.337,101.549 82.546,102.341 U1.41@82.546,103.732 ; v1@96.059,91.443 ccw(c95.377,92.126) 96.342,92.126 ccw(c97.308,92.126) v1@96.625,91.443 ; v1(96.342,91.161) 96.342,103.53 97.536,104.724 106.807,104.724 107.556,105.473 107.556,108.509 107.759,108.712 ; P2.10@107.985,108.54 ccw(c107.759,108.478) 107.759,108.712 ; P2.10@107.985,108.884 cw(c107.759,108.946) 107.759,108.712 ; P2.10@108.712,108.712 107.759,108.712
  Bottom Layer w0.2: v1(82.118,93.523) 93.98,93.523 v1(96.342,91.161) ; v1@82.401,93.24 cw(c83.084,92.557) 83.084,93.523 cw(c83.084,94.488) v1@82.401,93.806 ; v1@95.942,91.161 ccw(c94.977,91.161) 95.659,91.843 ccw(c96.342,92.526) v1@96.342,91.561
A30: P2.11 U1.42 | length 59.5
  Top Layer w0.2: U1.42@83.046,103.732 83.046,105.054 v1(84.545,106.553) ; U1.42@83.071,104.882 cw(c83.548,104.882) 83.211,105.219 ; v1@84.145,106.553 cw(c83.179,106.553) 83.862,105.87 cw(c84.545,105.187) v1@84.545,106.153 ; v1@101.571,94.39 ccw(c100.152,95.809) 102.159,95.809 ; v1@101.713,94.248 ccw(c100.635,95.326) 102.159,95.326 ; 102.159,94.843 cw(c101.118,94.843) v1(101.854,94.107) 102.133,94.107 102.159,94.132 102.159,102.235 102.413,102.489 109.855,102.489 109.862,102.496 109.862,104.851 108.712,106.001 P2.11@108.712,106.172 ; P2.11@108.812,105.522 cw(c108.812,104.606) 109.459,105.254 ; P2.11@109.054,106.111 ccw(c109.693,105.951) P2.11@109.227,105.486 ; P2.11@109.248,106.063 ccw(c110.092,105.851) 109.477,105.236 ; P2.11@109.442,106.014 ccw(c110.491,105.751) 109.727,104.987
  Bottom Layer w0.2: v1@84.545,106.153 cw(c84.545,105.649) 84.901,106.005 ; v1(84.545,106.553) 84.545,106.362 96.774,94.132 101.829,94.132 v1(101.854,94.107) ; v1@84.745,106.553 ccw(c85.689,106.553) 85.021,105.885 ; v1@84.945,106.553 ccw(c86.372,106.553) 85.363,105.544 ; 100.827,94.132 cw(c100.827,93.08) v1@101.571,93.824 ; 100.95,94.132 ccw(c100.95,95.011) v1@101.571,94.39 ; 101.31,94.132 cw(c101.31,93.563) v1@101.713,93.966
A31: P2.12 U1.52 | length 56.4
  Top Layer w0.2: U1.52@88.292,107.478 91.359,107.478 94.037,104.801 94.037,90.856 93.853,90.672 93.853,88.697 94.285,88.265 96.241,88.265 97.384,89.408 97.384,102.667 98.349,103.632 P2.12@108.712,103.632 ; P2.12@108.152,103.172 ccw(c107.043,102.063) 107.043,103.632 ccw(c107.043,105.201) P2.12@108.152,104.092 ; P2.12@108.294,103.314 ccw(c107.526,102.546) 107.526,103.632 ccw(c107.526,104.718) P2.12@108.294,103.95
AD4: P2.13 U1.3 | length 58.9
  Top Layer w0.2: U1.3@85.046,115.724 85.046,120.835 86.538,122.326 86.538,126.67 v1(85.522,127.686) ; v1@85.522,127.286 cw(c85.522,126.32) 86.205,127.003 cw(c86.887,127.686) v1@85.922,127.686
  Bottom Layer w0.2: v1@85.522,127.286 cw(c85.522,126.32) 86.205,127.003 cw(c86.887,127.686) v1@85.922,127.686 ; v1(85.522,127.686) 86.782,126.426 91.837,126.426 96.723,121.539 101.041,121.539 106.254,116.326 107.364,116.326 107.556,116.134 107.556,101.397 107.861,101.092 P2.13@108.712,101.092
AD5: P2.14 U1.4 | length 69.8
  Top Layer w0.2: v1(82.804,110.998) 83.058,110.998 84.546,112.486 U1.4@84.546,115.724 ; v1@82.804,111.198 ccw(c82.804,112.294) 83.579,111.519 ; v1@82.804,111.398 ccw(c82.804,112.977) 83.92,111.86 ; v1@83.204,110.998 cw(c83.556,110.998) 83.307,111.247
  Bottom Layer w0.2: v1(82.804,110.998) 83.337,111.531 84.988,111.531 85.319,111.201 85.319,110.167 83.566,108.414 83.566,104.597 94.666,93.497 100.584,93.497 107.315,86.766 107.315,85.225 107.958,84.582 109.855,84.582 110.287,85.014 110.287,97.993 109.728,98.552 ; P2.14@108.712,98.552 109.728,98.552 ; P2.14@109.426,98.337 cw(c109.728,98.232) 109.728,98.552 ; P2.14@109.426,98.767 ccw(c109.728,98.872) 109.728,98.552
AD6: P2.15 U1.5 | length 53.3
  Top Layer w0.2: v1@83.763,118.617 cw(c83.08,117.934) 84.046,117.934 cw(c85.012,117.934) v1@84.329,118.617 ; U1.5@84.046,115.724 v1(84.046,118.9)
  Bottom Layer w0.2: v1@84.187,119.041 ccw(c85.21,120.064) 85.21,118.618 ; v1@84.329,119.183 ccw(c85.692,120.546) 85.692,118.618 ; 84.727,118.618 cw(c84.727,119.581) v1(84.046,118.9) 84.328,118.618 87.999,118.618 89.065,117.552 89.065,116.89 89.027,116.852 89.027,105.81 98.825,96.012 P2.15@108.712,96.012 ; P2.15@108.152,95.552 ccw(c107.043,94.443) 107.043,96.012 ccw(c107.043,97.581) P2.15@108.152,96.472 ; P2.15@108.294,95.694 ccw(c107.526,94.926) 107.526,96.012 ccw(c107.526,97.098) P2.15@108.294,96.33
AD7: P2.16 U1.6 | length 58.7
  Top Layer w0.2: v1@83.029,113.059 ccw(c82.348,113.741) 83.312,113.741 ; v1(83.312,112.776) 83.312,113.741 ; U1.6@83.546,115.724 83.546,113.975 83.312,113.741 ; v1@83.595,113.059 cw(c84.276,113.741) 83.312,113.741
  Bottom Layer w0.2: v1@83.029,113.059 ccw(c82.348,113.741) 83.312,113.741 ; v1(83.312,112.776) 83.312,113.741 ; v1@83.595,113.059 cw(c84.276,113.741) 83.312,113.741 ; P2.16@108.712,93.472 109.88,93.269 109.88,87.274 109.728,87.122 107.798,87.122 102.968,91.951 102.968,94.691 102.512,95.147 96.712,95.147 86.208,105.652 86.208,111.684 84.125,113.767 83.337,113.767 83.312,113.741 ; P2.16@109.242,93.603 ccw(c109.626,93.72) P2.16@109.557,93.325 ; P2.16@109.315,93.06 cw(c109.775,92.683) 109.877,93.269 cw(c109.974,93.826) P2.16@109.434,93.661
ADPWR: C2.1 C3.2 DIP.5 P2.18 U1.1 | length 145.3
  Top Layer w0.2: v1(83.337,132.613) 85.395,132.613 86.538,131.47 86.538,129.616 88.011,128.143 DIP.5@88.011,122.809 ; v1@83.62,132.331 cw(c84.303,131.648) 84.303,132.613 cw(c84.303,133.579) v1@83.62,132.896 ; U1.1@86.046,115.724 86.046,117.474 87.351,118.779 ; 87.503,117.678 ccw(c87.865,118.04) v1@88.089,117.58 ; DIP.5@87.551,122.349 cw(c86.442,121.24) 88.011,121.24 cw(c89.58,121.24) DIP.5@88.471,122.349 ; DIP.5@87.551,123.269 ccw(c86.442,124.378) 88.011,124.378 ccw(c89.58,124.378) DIP.5@88.471,123.269 ; DIP.5@87.693,122.491 cw(c86.925,121.723) 88.011,121.723 cw(c89.097,121.723) DIP.5@88.329,122.491 ; DIP.5@87.693,123.127 ccw(c86.925,123.895) 88.011,123.895 ccw(c89.097,123.895) DIP.5@88.329,123.127 ; 87.701,117.48 ccw(c87.995,117.774) v1@88.177,117.401 ; v1(88.265,117.221) 87.96,117.221 87.351,117.831 87.351,118.779 ; 87.351,118.779 87.351,122.149 DIP.5@88.011,122.809 ; 87.351,118.779 88.011,119.439 DIP.5@88.011,122.809
  Bottom Layer w0.2: C3.2@53.594,138.086 cw(c53.594,136.336) 54.832,137.573 cw(c56.069,138.811) 54.319,138.811 cw(c56.069,138.811) 54.832,140.049 cw(c53.594,141.286) C3.2@53.594,139.536 ; C3.2@53.594,138.286 cw(c53.594,137.019) 54.49,137.915 cw(c55.386,138.811) 54.119,138.811 cw(c55.386,138.811) 54.49,139.707 cw(c53.594,140.603) C3.2@53.594,139.336 ; C2.1@61.367,144.663 ccw(c60.471,143.767) 60.471,145.034 ccw(c60.471,146.301) C2.1@61.367,145.405 ; C2.1@61.508,144.804 ccw(c60.953,144.249) 60.953,145.034 ccw(c60.953,145.819) C2.1@61.508,145.264 ; C2.1@61.738,145.034 59.817,145.034 C3.2@53.594,138.811 55.423,136.982 62.738,136.982 67.208,132.512 73.66,132.512 76.81,129.362 78.435,129.362 79.121,130.048 79.121,132.715 79.883,133.477 83.312,133.477 83.337,133.452 ; v1@83.086,132.924 ccw(c82.659,133.452) 83.337,133.452 ; v1(83.337,132.613) 83.337,133.452 ; v1@83.589,132.924 cw(c84.016,133.452) 83.337,133.452 ; 87.503,116.154 ccw(c86.608,117.049) v1@87.867,117.18 ; 87.8,116.451 ccw(c87.146,117.105) v1@88.066,117.2 ; 88.097,116.748 ccw(c87.685,117.161) v1(88.265,117.221) 88.265,116.916 87.351,116.002 87.351,106.045 97.815,95.58 102.692,95.58 107.544,90.729 107.544,88.595 107.747,88.392 ; P2.18@107.988,88.211 ccw(c107.747,88.141) 107.747,88.392 ; P2.18@107.988,88.573 cw(c107.747,88.643) 107.747,88.392 ; P2.18@108.712,88.392 107.747,88.392
DDM: C9.1 R5.2 U1.56 | length 73.5
  Top Layer w0.2: U1.56@88.292,109.478 84.125,109.478 83.63,109.973 83.63,110.947 91.618,118.935 91.618,125.149 86.944,129.822 86.944,141.427 92.329,146.812 98.044,146.812 ; C9.1@98.463,145.711 ccw(c97.026,145.794) 98.044,146.812 ; C9.1@98.663,145.699 ccw(c97.622,145.76) 98.359,146.497 ccw(c99.096,147.234) C9.1@99.157,146.193 ; C9.1@99.145,146.393 cw(c99.062,147.83) 98.044,146.812 ; C9.1@99.187,144.944 cw(c99.187,143.194) 100.425,144.431 cw(c101.662,145.669) C9.1@99.912,145.669 ; C9.1@99.187,145.144 cw(c99.187,143.877) 100.083,144.773 cw(c100.979,145.669) C9.1@99.712,145.669 ; R5.2@100.16,142.41 ccw(c99.135,143.435) 100.584,143.435 ccw(c102.033,143.435) R5.2@101.008,142.41 ; R5.2@100.301,142.269 ccw(c99.618,142.952) 100.584,142.952 ccw(c101.55,142.952) R5.2@100.867,142.269 ; R5.2@100.584,141.986 100.584,144.272 C9.1@99.187,145.669 98.044,146.812
DDP: C9.2 R3.2 R4.2 U1.57 | length 89.2
  Top Layer w0.2: U1.57@88.292,109.978 93.526,109.978 93.726,109.778 93.726,108.255 94.717,107.264 v1(96.672,107.264) ; v1(95.733,108.864) 100.584,113.716 100.584,115.418 100.178,115.824 99.162,115.824 98.316,116.67 98.316,120.973 98.755,121.412 99.847,121.412 100.584,122.149 100.584,124.435 97.028,127.991 97.028,136.398 R4.2@102.616,141.986 ; v1@95.733,109.264 ccw(c95.733,110.23) 96.415,109.547 ccw(c97.098,108.864) v1@96.133,108.864 ; v1@96.39,106.981 ccw(c95.707,106.299) 95.707,107.264 ccw(c95.707,108.23) v1@96.39,107.547 ; R4.2@102.016,141.986 cw(c100.567,141.986) 101.592,140.962 cw(c102.616,139.937) R4.2@102.616,141.386 ; R4.2@102.216,141.986 cw(c101.25,141.986) 101.933,141.303 cw(c102.616,140.62) R4.2@102.616,141.586
  Bottom Layer w0.2: v1@95.733,108.464 cw(c95.733,107.499) 96.415,108.182 cw(c97.098,108.864) v1@96.133,108.864 ; v1(95.733,108.864) 96.672,107.925 ; v1@96.487,107.619 ccw(c96.327,107.925) 96.672,107.925 ; C9.2@96.647,144.944 cw(c96.647,143.194) 97.885,144.431 cw(c99.122,145.669) C9.2@97.372,145.669 ; C9.2@96.647,145.144 cw(c96.647,143.877) 97.543,144.773 cw(c98.439,145.669) C9.2@97.172,145.669 ; C9.2@96.647,145.669 98.527,143.789 100.813,143.789 R4.2@102.616,141.986 R3.2@104.648,141.986 ; v1(96.672,107.264) 96.672,107.925 ; v1@96.858,107.619 cw(c97.018,107.925) 96.672,107.925 ; R4.2@102.016,141.986 ccw(c100.567,141.986) 101.592,143.01 ccw(c102.616,144.035) R4.2@102.616,142.586 ; R4.2@102.216,141.986 ccw(c101.25,141.986) 101.933,142.669 ccw(c102.616,143.352) R4.2@102.616,142.386 ; R4.2@102.899,141.703 cw(c103.582,141.02) 103.582,141.986 cw(c103.582,142.952) R4.2@102.899,142.269 ; R4.2@103.04,141.562 cw(c104.065,140.537) 104.065,141.986 cw(c104.065,143.435) R4.2@103.04,142.41 ; R3.2@104.224,141.562 ccw(c103.199,140.537) 103.199,141.986 ccw(c103.199,143.435) R3.2@104.224,142.41 ; R3.2@104.365,141.703 ccw(c103.682,141.02) 103.682,141.986 ccw(c103.682,142.952) R3.2@104.365,142.269
ERASE: DIP.2 U1.55 | length 37.3
  Top Layer w0.2: U1.55@88.292,108.978 v1(92.926,108.978) ; v1@92.643,108.695 ccw(c91.96,108.012) 91.96,108.978 ccw(c91.96,109.944) v1@92.643,109.261
  Bottom Layer w0.2: DIP.2@80.391,122.809 82.001,124.419 86.895,124.419 86.921,124.393 86.921,121.791 88.894,119.818 89.524,119.818 90.488,118.854 90.488,111.416 v1(92.926,108.978) ; DIP.2@80.391,123.259 ccw(c80.391,124.345) 81.159,123.577 ccw(c81.927,122.809) DIP.2@80.841,122.809 ; DIP.2@80.391,123.459 ccw(c80.391,125.028) 81.501,123.919 ccw(c82.61,122.809) DIP.2@81.041,122.809 ; v1@92.526,108.978 ccw(c91.56,108.978) 92.243,109.661 ccw(c92.926,110.344) v1@92.926,109.378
